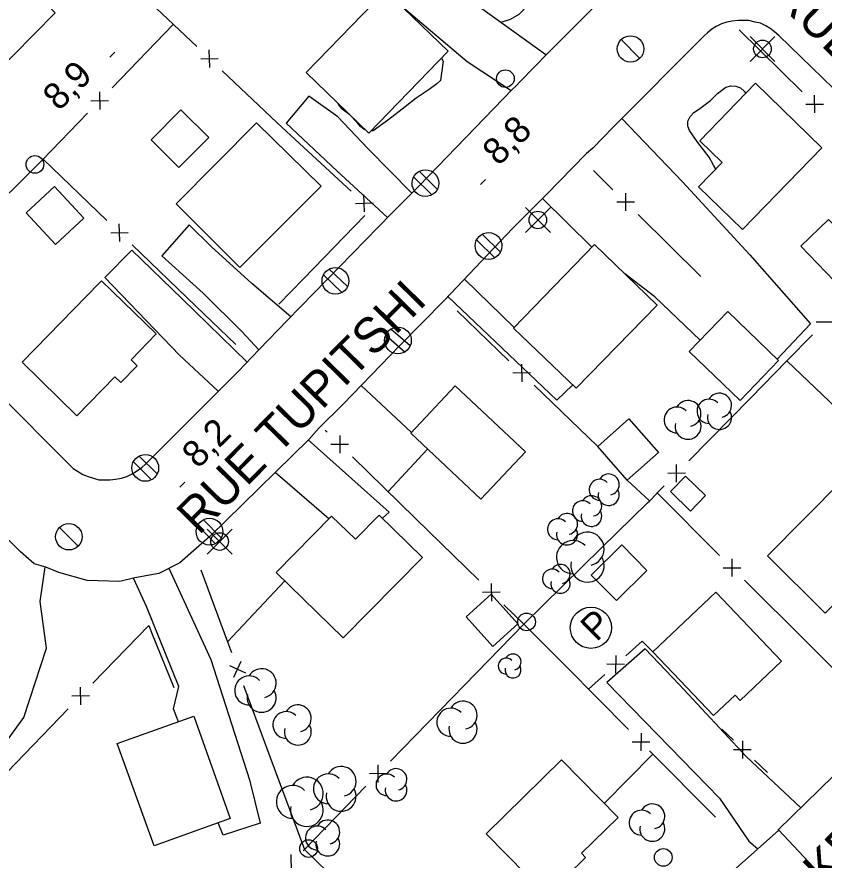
# Model space of a CAD drawing. Extents: x 381879 to 384696, y 5564785 to 5567594.
# Drawn here: x 383240.4 to 383331.9, y 5565383.1 to 5565478.7 of the extents above; entities that cross this region are included whole.
import ezdxf

# ---------------------------------------------------------------- set-up
doc = ezdxf.new("R2010")
doc.units = 0
for name, color, linetype in [('Niveau 1', 7, 'Continuous'), ('Niveau 19', 7, 'Continuous'), ('Niveau 21', 7, 'Continuous'), ('Niveau 3', 7, 'Continuous'), ('Niveau 31', 7, 'Continuous'), ('Niveau 36', 7, 'Continuous'), ('Niveau 37', 7, 'Continuous'), ('Niveau 38', 7, 'Continuous'), ('Niveau 44', 7, 'Continuous')]:
    doc.layers.add(name, color=color, linetype=linetype)

msp = doc.modelspace()

# ---------------------------------------------------------------- linework, layer by layer
at = {"layer": 'Niveau 1'}
for points in [[(383298.58, 5565480.26), (383297.33, 5565478.98), (383296.35, 5565478.4), (383295.27, 5565478.06)], [(383288.76, 5565473.67), (383288.43, 5565471.48), (383288.04, 5565471.11), (383287.15, 5565470.46), (383285.7, 5565469.48), (383284.44, 5565468.52), (383282.57, 5565467.05), (383280.81, 5565465.8), (383280.59, 5565465.8)], [(383288.55, 5565474.03), (383288.76, 5565473.67)], [(383317.59, 5565464.45), (383316.65, 5565465.81), (383316.49, 5565466.3), (383316.47, 5565466.88), (383316.73, 5565467.42), (383317.17, 5565467.85), (383317.68, 5565468.19), (383319.06, 5565469.24), (383319.84, 5565470.03), (383320.79, 5565470.72), (383321.34, 5565470.89), (383321.9, 5565470.84), (383322.45, 5565470.64), (383322.9, 5565470.26), (383323.1, 5565470.1)], [(383278.15, 5565467.59), (383277.3, 5565468.25), (383276.96, 5565468.62), (383276.83, 5565468.87)], [(383279.89, 5565465.9), (383279.8, 5565465.92), (383279.37, 5565466.26), (383278.98, 5565466.74), (383278.16, 5565467.58)], [(383319.63, 5565461.45), (383319.38, 5565461.88), (383318.89, 5565462.78), (383317.59, 5565464.45)]]:
    msp.add_lwpolyline(points, dxfattribs=at)
at = {"layer": 'Niveau 19'}
for points in [[(383300.39, 5565474.39), (383293.12, 5565479.61), (383289.65, 5565483.01), (383287, 5565485.32), (383283.17, 5565480.75)], [(383283.88, 5565480.06), (383291.48, 5565473.65), (383296.45, 5565470.34)], [(383285.21, 5565458.71), (383280.2, 5565463.77), (383276.8, 5565467.37), (383273.5, 5565469.72), (383270.94, 5565466.64), (383276.69, 5565461.24), (383282.45, 5565455.94)], [(383308.98, 5565467.18), (383315.87, 5565459.99), (383323.49, 5565451.72), (383330.39, 5565443.89), (383326.61, 5565439.89)], [(383305.59, 5565452.58), (383300.01, 5565458.11)], [(383271.47, 5565444.68), (383267.06, 5565448.48), (383262.45, 5565452.65), (383259.97, 5565455.14), (383256.87, 5565451.6), (383261.54, 5565447.37), (383265.93, 5565443.02), (383267.86, 5565440.96)], [(383266.52, 5565439.56), (383259.15, 5565446.75), (383253.47, 5565452.24), (383250.41, 5565449.14), (383258.86, 5565440.34), (383263.26, 5565436.26)], [(383291.15, 5565448.97), (383296.79, 5565443.49)], [(383317.87, 5565442.04), (383312.74, 5565446.96), (383309.33, 5565449.57)], [(383303.42, 5565436.96), (383301.64, 5565435.23), (383289.29, 5565447.01)], [(383279.45, 5565436.91), (383285.16, 5565431.58)], [(383273.46, 5565430.76), (383282.63, 5565422.55), (383281.85, 5565421.85)], [(383286.98, 5565429.7), (383282.5, 5565424.88)], [(383275.78, 5565421.78), (383269.69, 5565427.06)], [(383257.66, 5565416.18), (383262.4, 5565405.84), (383266.79, 5565392.2), (383268, 5565387.3), (383263.8, 5565385.92), (383263.25, 5565387.31)], [(383258.75, 5565398.78), (383258.18, 5565400.24), (383258.79, 5565402.78), (383255.13, 5565411.86), (383253.66, 5565415.07)], [(383329.27, 5565389.03), (383323.07, 5565394.83), (383315.5, 5565402.99), (383311.64, 5565407.04), (383307.3, 5565403.24), (383320.07, 5565390.12), (383323.37, 5565385.23), (383324.42, 5565384.37)]]:
    msp.add_lwpolyline(points, dxfattribs=at)
at = {"layer": 'Niveau 21'}
for points in [[(383300.6, 5565474.6), (383313.4, 5565487.4), (383327.8, 5565502.4)], [(383326.8, 5565476.6), (383326.3, 5565477), (383325.8, 5565477.4), (383325.3, 5565477.7), (383324.7, 5565478), (383324.1, 5565478.1), (383323.4, 5565478.3), (383322.8, 5565478.3), (383322.2, 5565478.3), (383321.5, 5565478.2), (383320.9, 5565478.1), (383320.3, 5565477.9), (383319.7, 5565477.6), (383319.2, 5565477.3), (383318.7, 5565476.9), (383318.3, 5565476.5)], [(383318.3, 5565476.5), (383308, 5565466.2)], [(383338, 5565465.7), (383326.8, 5565476.6)], [(383297.5, 5565471.4), (383300.6, 5565474.6)], [(383296.6, 5565470.5), (383297, 5565470.9), (383297.5, 5565471.4)], [(383286, 5565459.5), (383296.6, 5565470.5)], [(383308, 5565466.2), (383305.7, 5565463.8)], [(383208.2, 5565465.9), (383218.5, 5565455.2), (383238.3, 5565436), (383246.3, 5565428)], [(383305, 5565463.2), (383303.4, 5565461.6)], [(383305.7, 5565463.8), (383305, 5565463.2)], [(383303.4, 5565461.6), (383300.5, 5565458.6)], [(383282.9, 5565456.4), (383286, 5565459.5)], [(383300.5, 5565458.6), (383296.6, 5565454.7), (383288.9, 5565446.6)], [(383271.1, 5565444.3), (383282.9, 5565456.4)], [(383288.9, 5565446.6), (383283.8, 5565441.4), (383277.4, 5565434.8)], [(383267.9, 5565441), (383271.1, 5565444.3)], [(383255, 5565428), (383265.5, 5565438.5), (383267.9, 5565441)], [(383277.4, 5565434.8), (383274.7, 5565432.1)], [(383274.7, 5565432.1), (383273.5, 5565430.8), (383262.3, 5565419.8), (383258.9, 5565416.8)], [(383246.3, 5565428), (383246.8, 5565427.5), (383247.3, 5565427.2), (383247.9, 5565426.8), (383248.5, 5565426.6), (383249.1, 5565426.4), (383249.7, 5565426.2), (383250.4, 5565426.2), (383251, 5565426.2), (383251.6, 5565426.3), (383252.3, 5565426.4), (383252.9, 5565426.6), (383253.5, 5565426.9), (383254, 5565427.2), (383254.6, 5565427.6), (383255, 5565428)], [(383326.66, 5565386.49), (383336.1, 5565395.7), (383349.8, 5565409.8), (383361.81, 5565424.11)], [(383240.8, 5565418.1), (383237.7, 5565421.2), (383236.8, 5565422)], [(383243.7, 5565416.3), (383242.4, 5565416.7), (383240.8, 5565418.1)], [(383287.03, 5565366.47), (383272.7, 5565366.43), (383260.45, 5565365.37), (383253.79, 5565365.29), (383248.29, 5565370.63), (383238.04, 5565381.44), (383233.93, 5565386.75), (383234.49, 5565390.02), (383241.22, 5565399.26), (383243.8, 5565407.14), (383243.07, 5565412.42), (383243.64, 5565416.32)], [(383253.8, 5565415.1), (383252.1, 5565414.7), (383248.4, 5565414.8), (383245.2, 5565415.7), (383243.7, 5565416.3)], [(383258.9, 5565416.8), (383256.5, 5565415.6), (383253.8, 5565415.1)], [(383326.66, 5565386.49), (383326.75, 5565386.58)], [(383300.51, 5565367.8), (383306.69, 5565374.13), (383311.42, 5565375.12), (383316.64, 5565378.03), (383321.6, 5565381.88), (383326.8, 5565386.47)], [(383326.8, 5565386.47), (383332.98, 5565379.87)]]:
    msp.add_lwpolyline(points, dxfattribs=at)
at = {"layer": 'Niveau 3'}
for p, q in [((383250.96, 5565474.13), (383251.53, 5565474.7)), ((383292.97, 5565459.68), (383293.54, 5565460.25)), ((383258.91, 5565425.37), (383259.48, 5565425.94))]:
    msp.add_line(p, q, dxfattribs=at)
at = {"layer": 'Niveau 31'}
for points in [[(383216.34, 5565471.39), (383223.75, 5565464.09), (383229.7, 5565470.13), (383231.34, 5565468.51), (383236.13, 5565473.36), (383237.59, 5565471.92), (383244.76, 5565479.18), (383237.43, 5565486.42), (383231.57, 5565480.49), (383229.98, 5565482.06), (383224.2, 5565476.21), (383222.63, 5565477.76)], [(383282.2, 5565481.7), (383289.3, 5565474.8), (383280.3, 5565465.5), (383273.2, 5565472.4)], [(383331.67, 5565463.87), (383322.68, 5565454.61), (383317.69, 5565459.45), (383320.36, 5565462.2), (383317.82, 5565464.66), (383324.13, 5565471.17)], [(383255.64, 5565464.77), (383259.03, 5565468.18), (383262.18, 5565465.04), (383258.79, 5565461.63)], [(383267.6, 5565466.7), (383274.9, 5565459.5), (383265.7, 5565450.3), (383258.5, 5565457.5)], [(383244.7, 5565459.47), (383248.01, 5565455.88), (383244.79, 5565452.91), (383241.48, 5565456.5)], [(383332.42, 5565455.73), (383336.2, 5565451.81), (383333.05, 5565448.78), (383329.27, 5565452.7)], [(383303.8, 5565436.6), (383296.7, 5565443.4), (383305.9, 5565452.9), (383313, 5565446)], [(383249.81, 5565448.53), (383241.01, 5565439.55), (383247.21, 5565433.47), (383251.54, 5565437.89), (383252.21, 5565437.23), (383254.08, 5565439.13), (383253.38, 5565439.81), (383256.23, 5565442.75), (383250.03, 5565448.76)], [(383321.01, 5565445.29), (383326.76, 5565439.75), (383322.39, 5565435.22), (383316.64, 5565440.76)], [(383290.11, 5565436.86), (383298.07, 5565429.4), (383293.03, 5565424.03), (383285.07, 5565431.49)], [(383309.79, 5565433.11), (383313.14, 5565429.31), (383309.61, 5565426.19), (383306.26, 5565429.99)], [(383316.19, 5565426.63), (383318.47, 5565424.42), (383316.77, 5565422.67), (383314.49, 5565424.88)], [(383334.02, 5565426.19), (383325.49, 5565417.6), (383332.03, 5565411.1), (383336.11, 5565415.2), (383336.44, 5565414.88), (383340.92, 5565419.49)], [(383277.4, 5565408.3), (383269.8, 5565415.7), (383276.1, 5565422.1), (383278.8, 5565419.5), (383281.5, 5565422.2), (383286.4, 5565417.4)], [(383305.51, 5565415.42), (383308.98, 5565418.84), (383311.84, 5565415.94), (383308.37, 5565412.52)], [(383319.64, 5565413.49), (383312.51, 5565406.72), (383319.38, 5565399.49), (383321.82, 5565401.81), (383322.41, 5565401.19), (383327.1, 5565405.65)], [(383291.34, 5565410.66), (383294.36, 5565407.33), (383297.2, 5565409.9), (383294.18, 5565413.23)], [(383251.8, 5565396.3), (383260.5, 5565399.4), (383264.6, 5565387.8), (383256, 5565384.7)], [(383302.16, 5565394.47), (383293.61, 5565386.07), (383300.48, 5565379.07), (383304.89, 5565383.4), (383304.42, 5565383.88), (383308.56, 5565387.94)]]:
    msp.add_lwpolyline(points, close=True, dxfattribs=at)
at = {"layer": 'Niveau 36'}
for p, q in [((383326.35, 5565476.47), (383323.53, 5565473.65)), ((383326.35, 5565473.65), (383323.53, 5565476.47)), ((383311.05, 5565474), (383308.93, 5565476.12)), ((383288.08, 5565459.17), (383286.02, 5565461.21)), ((383285.38, 5565460.55), (383287.44, 5565458.51)), ((383300.89, 5565457.08), (383298.07, 5565454.26)), ((383300.89, 5565454.26), (383298.07, 5565457.08)), ((383295.24, 5565452.03), (383293.18, 5565454.07)), ((383292.54, 5565453.41), (383294.6, 5565451.37)), ((383277.89, 5565448.12), (383275.79, 5565450.12)), ((383275.17, 5565449.44), (383277.27, 5565447.44)), ((383285.01, 5565441.4), (383282.82, 5565443.31)), ((383282.23, 5565442.6), (383284.42, 5565440.69)), ((383256.33, 5565426.89), (383254.26, 5565428.92)), ((383253.63, 5565428.25), (383255.7, 5565426.22)), ((383260.92, 5565421.04), (383262.95, 5565418.97)), ((383263.6, 5565419.62), (383261.57, 5565421.69)), ((383247.39, 5565418.69), (383245.27, 5565420.81)), ((383264.82, 5565420.62), (383262, 5565417.8)), ((383264.82, 5565417.8), (383262, 5565420.62))]:
    msp.add_line(p, q, dxfattribs=at)
for centre, radius in [((383309.982, 5565475.065), 1.5), ((383324.932, 5565475.065), 1), ((383295.793, 5565471.7), 1), ((383242.473, 5565461.97), 1), ((383299.472, 5565455.675), 1), ((383246.322, 5565419.755), 1.5), ((383263.402, 5565419.215), 1), ((383298.193, 5565410.1), 1), ((383273.493, 5565384.4), 1), ((383313.693, 5565383.4), 1)]:
    msp.add_circle(centre, radius, dxfattribs=at)
for centre, major_axis, ratio in [((383286.732, 5565459.852), (0.017, 1.517), 0.999984), ((383293.888, 5565452.728), (-0.017, -1.517), 0.999984), ((383276.532, 5565448.772), (0.012, 1.517), 0.999981), ((383283.618, 5565442.008), (-0.022, -1.517), 0.999985), ((383254.982, 5565427.562), (0.013, 1.517), 0.999981), ((383262.258, 5565420.338), (0.014, 1.517), 0.999984)]:
    msp.add_ellipse(centre, major_axis=major_axis, ratio=ratio, dxfattribs=at)
at = {"layer": 'Niveau 37'}
for p, q in [((383262.29, 5565472.96), (383262.24, 5565474.96)), ((383261.26, 5565473.93), (383263.26, 5565473.98)), ((383249.81, 5565470.22), (383249.85, 5565468.21)), ((383330.85, 5565467.81), (383330.83, 5565469.81)), ((383248.83, 5565469.2), (383250.83, 5565469.23)), ((383329.84, 5565468.8), (383331.84, 5565468.82)), ((383279.84, 5565456.58), (383279.76, 5565458.58)), ((383309.41, 5565458.71), (383309.42, 5565456.7)), ((383278.8, 5565457.54), (383280.8, 5565457.62)), ((383310.42, 5565457.71), (383308.41, 5565457.7)), ((383252.08, 5565453.24), (383252.04, 5565455.24)), ((383251.06, 5565454.22), (383253.06, 5565454.26)), ((383333.01, 5565444.09), (383331.01, 5565444.07)), ((383297.62, 5565439.33), (383297.65, 5565437.33)), ((383298.63, 5565438.35), (383296.63, 5565438.31)), ((383277.02, 5565431.22), (383277.04, 5565429.22)), ((383278.03, 5565430.23), (383276.03, 5565430.21)), ((383315.2, 5565425.95), (383315.18, 5565427.95)), ((383316.19, 5565426.96), (383314.19, 5565426.94)), ((383321.49, 5565415.24), (383321.49, 5565417.24)), ((383320.49, 5565416.24), (383322.49, 5565416.24)), ((383294.19, 5565414.45), (383294.21, 5565412.45)), ((383295.2, 5565413.46), (383293.2, 5565413.44)), ((383308.3, 5565406.29), (383308.29, 5565404.29)), ((383264.53, 5565405.17), (383266.35, 5565404.34)), ((383265.02, 5565403.84), (383265.86, 5565405.66)), ((383309.29, 5565405.29), (383307.29, 5565405.3)), ((383247.67, 5565400.7), (383247.63, 5565402.7)), ((383248.65, 5565401.72), (383246.65, 5565401.68)), ((383311.17, 5565397.47), (383311.16, 5565395.47)), ((383312.16, 5565396.47), (383310.16, 5565396.48)), ((383322.67, 5565396.6), (383322.66, 5565394.6)), ((383323.66, 5565395.6), (383321.66, 5565395.61)), ((383281.39, 5565391.89), (383281.37, 5565393.89)), ((383282.38, 5565392.9), (383280.38, 5565392.88)), ((383271.48, 5565383.73), (383271.51, 5565381.72))]:
    msp.add_line(p, q, dxfattribs=at)
for points in [[(383253.56, 5565482.22), (383260.81, 5565475.34)], [(383258.16, 5565477.85), (383251.22, 5565470.65)], [(383322.28, 5565477.22), (383329.42, 5565470.21)], [(383263.71, 5565472.58), (383269.89, 5565466.72), (383270.98, 5565465.71)], [(383248.44, 5565467.77), (383243.35, 5565462.5), (383241.45, 5565460.62)], [(383270.98, 5565465.71), (383278.33, 5565458.93)], [(383243.42, 5565462.57), (383250.62, 5565455.63)], [(383307.99, 5565459.11), (383305.8, 5565461.27)], [(383241.45, 5565460.62), (383234.33, 5565453.6)], [(383279.86, 5565456.18), (383272.9, 5565449)], [(383317.96, 5565449.28), (383310.84, 5565456.3)], [(383253.5, 5565452.85), (383260.7, 5565445.91)], [(383272.9, 5565449), (383270.11, 5565446.12)], [(383260.7, 5565445.91), (383265.23, 5565441.54)], [(383296.19, 5565439.72), (383290.34, 5565445.38)], [(383323.6, 5565435.52), (383327.7, 5565439.69), (383330.61, 5565442.65)], [(383327.7, 5565439.69), (383334.93, 5565432.78)], [(383306.26, 5565429.99), (383299.07, 5565436.94)], [(383316.59, 5565428.38), (383323.6, 5565435.52)], [(383275.6, 5565431.62), (383275.38, 5565431.83)], [(383285.62, 5565421.84), (383278.46, 5565428.82)], [(383309.61, 5565426.19), (383312.11, 5565423.82)], [(383306.69, 5565418.49), (383311.91, 5565423.61), (383312.11, 5565423.81), (383312.96, 5565424.68), (383312.98, 5565424.7), (383313, 5565424.72), (383313.79, 5565425.53)], [(383313, 5565424.72), (383320.07, 5565417.65)], [(383292.77, 5565414.85), (383285.62, 5565421.84)], [(383297.9, 5565409.86), (383306.69, 5565418.49)], [(383261.28, 5565416.01), (383264.29, 5565407.86), (383264.75, 5565406.63)], [(383264.29, 5565407.86), (383270.79, 5565414.74)], [(383322.9, 5565414.82), (383329.98, 5565407.76)], [(383302.71, 5565405), (383298.19, 5565409.56), (383297.89, 5565409.85), (383295.63, 5565412.05)], [(383249.04, 5565403.14), (383255.38, 5565409.71), (383255.7, 5565408.9)], [(383289.75, 5565401.49), (383297.9, 5565409.85)], [(383255.7, 5565408.9), (383258.21, 5565402.68)], [(383309.45, 5565406.26), (383311.3, 5565407.91), (383312.51, 5565406.72)], [(383329.98, 5565407.76), (383335.17, 5565402.57)], [(383309.75, 5565397.89), (383302.71, 5565405)], [(383305.2, 5565402.49), (383307.07, 5565404.15)], [(383266.13, 5565402.88), (383269.6, 5565393.5)], [(383282.78, 5565394.32), (383289.75, 5565401.49)], [(383239.32, 5565393.06), (383246.26, 5565400.26)], [(383320.34, 5565397.94), (383321.65, 5565396.69)], [(383319.61, 5565387.95), (383312.12, 5565395.5)], [(383307, 5565389.53), (383312.51, 5565395.11)], [(383324.04, 5565394.43), (383325.51, 5565393.03)], [(383269.6, 5565393.5), (383273.01, 5565384.29), (383272.88, 5565384.16)], [(383273.01, 5565384.29), (383279.99, 5565391.46)], [(383273.01, 5565384.29), (383276.98, 5565380.44)]]:
    msp.add_lwpolyline(points, dxfattribs=at)
at = {"layer": 'Niveau 38'}
msp.add_circle((383305.488, 5565409.434), 2.336, dxfattribs=at)
at = {"layer": 'Niveau 44'}
for centre, radius, start, end in [((383318.88, 5565433.978), 1.371, 44.11535, 269.80394), ((383320.059, 5565434.663), 1.371, 282.26915, 149.72624), ((383315.241, 5565433.002), 1.465, 44.11535, 269.80394), ((383316.501, 5565433.734), 1.465, 282.26915, 149.72624), ((383320.059, 5565433.292), 1.371, 166.93684, 29.62121), ((383316.501, 5565432.269), 1.465, 166.93684, 29.62121), ((383307.507, 5565425.685), 1.19, 282.26915, 149.72624), ((383306.484, 5565425.09), 1.19, 44.11535, 269.80394), ((383307.507, 5565424.495), 1.19, 166.93684, 29.62121), ((383305.551, 5565423.251), 1.163, 282.26915, 149.72624), ((383304.55, 5565422.669), 1.163, 44.11535, 269.80394), ((383302.787, 5565421.205), 1.19, 282.26915, 149.72624), ((383305.551, 5565422.087), 1.163, 166.93684, 29.62121), ((383301.764, 5565420.61), 1.19, 44.11535, 269.80394), ((383302.787, 5565420.015), 1.19, 166.93684, 29.62121), ((383305.1, 5565418.383), 1.888, 282.26915, 149.72624), ((383303.476, 5565417.439), 1.888, 44.11535, 269.80394), ((383305.1, 5565416.495), 1.888, 166.93684, 29.62121), ((383302.035, 5565415.534), 1.096, 282.26915, 149.72624), ((383301.092, 5565414.986), 1.096, 44.11535, 269.80394), ((383302.035, 5565414.438), 1.096, 166.93684, 29.62121), ((383295.88, 5565405.098), 0.909, 44.11535, 269.80394), ((383296.662, 5565405.552), 0.909, 282.26915, 149.72624), ((383268.173, 5565403.152), 1.646, 282.26915, 149.72624), ((383296.662, 5565404.644), 0.909, 166.93684, 29.62121), ((383266.758, 5565402.329), 1.646, 44.11535, 269.80394), ((383268.173, 5565401.506), 1.646, 166.93684, 29.62121), ((383290.991, 5565399.523), 1.593, 282.26915, 149.72624), ((383272.274, 5565399.173), 1.519, 282.26915, 149.72624), ((383289.621, 5565398.727), 1.593, 44.11535, 269.80394), ((383270.967, 5565398.414), 1.519, 44.11535, 269.80394), ((383272.274, 5565397.654), 1.519, 166.93684, 29.62121), ((383290.991, 5565397.931), 1.593, 166.93684, 29.62121), ((383277.184, 5565392.018), 1.693, 282.26915, 149.72624), ((383283.405, 5565392.243), 1.224, 282.26915, 149.72624), ((383273.293, 5565390.629), 1.861, 282.26915, 149.72624), ((383275.728, 5565391.171), 1.693, 44.11535, 269.80394), ((383282.352, 5565391.631), 1.224, 44.11535, 269.80394), ((383271.693, 5565389.698), 1.861, 44.11535, 269.80394), ((383283.405, 5565391.02), 1.224, 166.93684, 29.62121), ((383277.184, 5565390.325), 1.693, 166.93684, 29.62121), ((383273.293, 5565388.768), 1.861, 166.93684, 29.62121), ((383312.449, 5565388.045), 1.412, 282.26915, 149.72624), ((383311.235, 5565387.339), 1.412, 44.11535, 269.80394), ((383275.656, 5565386.276), 1.358, 282.26915, 149.72624), ((383274.488, 5565385.597), 1.358, 44.11535, 269.80394), ((383312.449, 5565386.634), 1.412, 166.93684, 29.62121), ((383275.656, 5565384.918), 1.358, 166.93684, 29.62121)]:
    msp.add_arc(centre, radius, start, end, dxfattribs=at)

# ---------------------------------------------------------------- texts
at = {"layer": 'Niveau 21'}
for s, rotation, p in [('RUE PAPINEAU', 315.52948, (383325.97, 5565480.91)), ('RUE TUPITSHI', 45.54919, (383261.06, 5565419.85)), ('RUE MCKENZIE', 46.07788, (383317.42, 5565364.56))]:
    msp.add_text(s, height=4.00002, rotation=rotation, dxfattribs=at).set_placement(p)
at = {"layer": 'Niveau 3'}
for s, p in [('8,9', (383245.19, 5565467.94)), ('8,8  ', (383295.02, 5565461.71)), ('8,2  ', (383260.96, 5565427.39))]:
    msp.add_text(s, height=3, rotation=44.7717, dxfattribs=at).set_placement(p)
at = {"layer": 'Niveau 38'}
msp.add_text('P', height=3, rotation=44.7717, dxfattribs=at).set_placement((383306.14, 5565407.76))

doc.saveas('drawing.dxf')
